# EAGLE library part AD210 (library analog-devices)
Precision, Wide Bandwidth 3-Port Isolation Amplifier Source: http://www.analog.com/static/imported-files/data_sheets/AD210.pdf
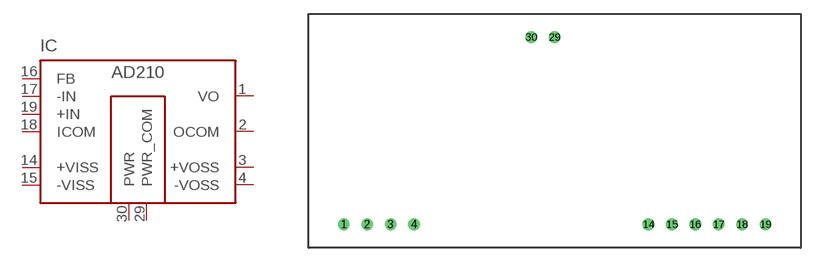
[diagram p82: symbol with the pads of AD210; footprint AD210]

Designator prefix IC

## AD210 (MF: ALTERA CORPORATION; MPN: AD210AN; OC_FARNELL: 3182034; OC_NEWARK: 05F6727)  [AD210]
1  VO  out
2  OCOM  out
3  +VOSS  out
4  -VOSS  out
14  +VISS  in
15  -VISS  in
16  FB  in
17  -IN  in
18  ICOM  in
19  +IN  in
29  PWR_COM  in
30  PWR  in

## Footprint AD210 (pad centres in mm)
Source: http://www.analog.com/static/imported-files/data_sheets/AD210.pdf
drill 0.7 pad 1.27 round: 1 -24.13,-10.16; 2 -21.59,-10.16; 3 -19.05,-10.16; 4 -16.51,-10.16; 14 8.89,-10.16; 15 11.43,-10.16; 16 13.97,-10.16; 17 16.51,-10.16; 18 19.05,-10.16; 19 21.59,-10.16; 29 -1.27,10.16; 30 -3.81,10.16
